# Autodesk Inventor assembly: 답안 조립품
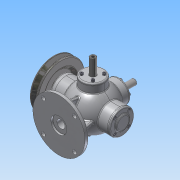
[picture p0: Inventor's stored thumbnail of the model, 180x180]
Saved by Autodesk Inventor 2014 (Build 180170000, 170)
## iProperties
Created: 2016-01
Part Number: 답안 조립품
Document SubType Name: Assembly
Designer: Administrator
Mass: 3770.68 g
Surface Area: 2411.01 cm^2
Volume: 903.659 cm^3
Density: 4.17268 g/cm^3
Author: Administrator
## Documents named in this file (17)
- C:\Users\Administrator\Desktop\360108V1012\답안 조립품.iam
- C:\Users\Administrator\Desktop\360108V1012\본체.ipt
- C:\Users\Administrator\Desktop\360108V1012\본체커버.ipt
- C:\Users\Administrator\Desktop\360108V1012\축.ipt
- C:\Users\Administrator\Desktop\360108V1012\베어링- 6202.ipt
- C:\Users\Administrator\Desktop\360108V1012\앞커버.ipt
- C:\Users\Administrator\Desktop\360108V1012\뒤커버.ipt
- C:\Users\Administrator\Desktop\360108V1012\키-4x4.ipt
- C:\Users\Administrator\Desktop\360108V1012\오일실.ipt
- C:\Users\Administrator\Desktop\360108V1012\볼트 M4x0.7.ipt
- C:\Users\Administrator\Desktop\360108V1012\V-벨트풀리.ipt
- C:\Users\Administrator\Desktop\360108V1012\와셔 8x17.ipt
- C:\Users\Administrator\Desktop\360108V1012\너트-M8x1.ipt
- C:\Users\Administrator\Desktop\360108V1012\슬라이드 커버.ipt
- C:\Users\Administrator\Desktop\360108V1012\슬라이드.ipt
- C:\Users\Administrator\Desktop\360108V1012\가변스프링.ipt
- C:\Users\Administrator\Desktop\360108V1012\16-가변스프링.ipt
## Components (20 placed, 4 different names)
1. V-벨트풀리:1 — 플러쉬:1, 각도:2
2. M4x0.7x12:17
3. 가변스프링:1
4. 16-가변스프링:1
5. M4x0.7x12:2
6. M4x0.7x12:3
7. M4x0.7x12:4
8. M4x0.7x12:5
9. M4x0.7x12:1
10. M4x0.7x12:6
11. M4x0.7x12:7
12. M4x0.7x12:8
13. M4x0.7x12:9
14. M4x0.7x12:11
15. M4x0.7x12:12
16. M4x0.7x12:13
17. M4x0.7x12:10
18. M4x0.7x12:14
19. M4x0.7x12:15
20. M4x0.7x12:16
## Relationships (2: Flush 1, Angle 1)
- 플러쉬:1 [Flush]: V-벨트풀리:1
- 각도:2 [Angle]: V-벨트풀리:1
